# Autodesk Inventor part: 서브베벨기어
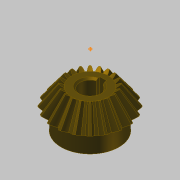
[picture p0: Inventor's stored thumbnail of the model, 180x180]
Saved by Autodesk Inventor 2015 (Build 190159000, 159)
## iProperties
Created: 2018-09
Part Number: 서브베벨기어
Material: 강철, 탄소
Document SubType Name: Modeling
Categories: <?xml version="1.0" encoding="UTF-16"?> <MemberInstance><Categories><FamilyTemplate><FamilyTemplateParameter ValueType="xs:double" Id="1" ObjectReferenceKey="da
Mass: 135.037 g
Surface Area: 63.6444 cm^2
Volume: 17.1585 cm^3
Density: 7.87 g/cm^3
Appearance: 얼룩무늬
CustomPartVersion: 1
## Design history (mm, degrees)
node "맨 위 점"
node "메쉬 평면2"
sketch "톱니 본체 스케치"
  geometry: L1 (0, 0)-(18.003, -31.331); L2 (18.003, -31.331)-(21.664, -28.891); L3 (21.664, -28.891)-(0, 0); L4 (20, -30)-(0, 0); L5 (10.813, -18.818)-(13.012, -17.352); L6 (18.003, -31.331)-(10.813, -18.818); L7 (21.664, -28.891)-(13.012, -17.352); L8 (0, -39.387)-(0, 6.564) reference; L9 (0, -30)-(21.664, -30)
  constraints: 16 end point, 4 point on line, 3 perpendicular, 2 collinear, 1 horizontal alignment, 1 vertical alignment
  dimensions: "d0" = 40 diameter of L4.start L8 (= da_de); "d1" = 36.00616 diameter of L1.end L8 (= da_dfe); "d2" = 43.3282 diameter of L2.end L8 (= da_dae); "d3" = 14.4 distance between parallel lines of L2 L5 (= da_b); "d4" = 28.8906 vertical distance of L2.end L1.start (= da_ve)
revolve "톱니 본체" sketch "톱니 본체 스케치" stored, may be unused: angle "d5" = 90 deg
node "시작점"
node "톱니 평면"
sketch "시작 스케치"
  geometry: L1 (0, -23.505)-(0, 10.645) reference; L2 (-0.834, -2.928)-(0.834, -2.928); A1 r 8.898 centre (-9.698, -3.713) between (-0.834, -2.928) and (-3.903, 3.04); A2 r 8.898 centre (9.698, -3.713) between (3.903, 3.04) and (0.834, -2.928); A3 r 27.357 centre (0, -24.037) between (3.903, 3.04) and (-3.903, 3.04); 1 further point
  constraints: 6 point on circle, 3 centre point, 3 symmetric about line, 2 end point, 1 coincident, 1 perpendicular, 1 other
  dimensions: "d7" = 8.89846 radius of A1 (= fd_rr); "d8" = 9.69794 horizontal distance of point (0, -24.037) A1.centre (= fd_x); "d9" = 20.32439 vertical distance of point (0, -24.037) A1.centre (= fd_y); "d57" = 27.35701 radius of A3 (= 0.5 x fd_dva + 0.3 x da_he); "d58" = 21.10901 distance from line of A3.centre L2 (= 0.5 x fd_dva - 1.12 x da_he)
node "끝점"
  node "끝 평면"
sketch "3D 스케치 오른쪽"
  node "Helical Curve Right" dims "d65" = 229.90621 (computed from da_dm, da_delta, da_beta), "d66" = 31.5, "d67" = 40 (= da_de), "d68" = -5.88003 (= -da_delta), "d69" = 12.16458 (computed from fd_loft, da_delta)
node "끝 평면 오른쪽"
sketch "끝 스케치 오른쪽"
  geometry: L1 (0, -22.649)-(0, 12.15) reference; L2 (-0.497, -1.72)-(0.497, -1.72); A1 r 5.299 centre (-5.775, -2.187) between (-0.497, -1.72) and (-2.324, 1.834); A2 r 5.299 centre (5.775, -2.187) between (2.324, 1.834) and (0.497, -1.72); A3 r 16.291 centre (0, -14.29) between (2.324, 1.834) and (-2.324, 1.834); 1 further point
  constraints: 6 point on circle, 3 centre point, 3 symmetric about line, 2 end point, 1 coincident, 1 perpendicular, 1 other
  dimensions: "d70" = 5.77526 horizontal distance of A3.centre A1.centre (computed from fd_x, fd_ratio); "d71" = 12.10346 vertical distance of point (0, -14.29) A1.centre (computed from fd_y, fd_ratio); "d72" = 5.29916 radius of A1 (computed from fd_rr, fd_ratio); "d73" = 12.57071 distance from line of point (0, -14.29) L2 (computed from d58, fd_ratio); "d74" = 16.29149 radius of A3 (computed from d57, fd_ratio)
feature "로프트 오른쪽" sketch "끝 스케치 오른쪽" dims "d75" = 0, "d77" = 0, "d79" = 0, "d80" = 90 deg, "d85" = 20, "d92" = 90 deg, "d93" = 90 deg, "da_teethtype" = 0 [user parameter]
sketch "3D 스케치 왼쪽"
  node "Helical Curve Left" dims "d26" = 229.90621 (computed from da_dm, da_delta, da_beta), "d27" = 12.16458 (computed from fd_loft, da_delta), "d28" = 40 (= da_de), "d29" = -5.88003 (= -da_delta)
node "끝 평면 왼쪽"
sketch "끝 스케치 왼쪽" dims "d56" = 10.82768 (derived)
  geometry: L1 (0, -35.087)-(0, 18.089) reference; L2 (-0.497, -1.716)-(0.497, -1.716); A1 r 5.299 centre (-5.775, -2.183) between (-0.497, -1.716) and (-2.324, 1.838); A2 r 5.299 centre (5.775, -2.183) between (2.324, 1.838) and (0.497, -1.716); A3 r 16.291 centre (0, -14.287) between (2.324, 1.838) and (-2.324, 1.838); 2 further points; 1 other entity
  constraints: 6 point on circle, 3 centre point, 3 symmetric about line, 2 end point, 1 coincident, 2 other
  dimensions: "d30" = 5.29916 radius of A1 (computed from fd_rr, fd_ratio); "d31" = 5.77526 horizontal distance of point (0, -14.287) A1.centre (computed from fd_x, fd_ratio); "d32" = 12.10346 vertical distance of A1.centre point (0, -14.287) (computed from fd_y, fd_ratio); "d61" = 16.29149 radius of A3 (computed from d57, fd_ratio); "d62" = 12.57071 distance from line of point (0, -14.287) L2 (computed from d58, fd_ratio)
feature "로프트 왼쪽" sketch "끝 스케치 왼쪽" dims "d35" = 0, "d37" = 0, "d39" = 0, "d40" = 90 deg, "d84" = 10, "d90" = 90 deg, "d91" = 90 deg, "da_teethtype" = 0 [user parameter]
sketch "본체 스케치"
  geometry: L1 (0, -35.038)-(0, -19.531) reference; L2 (18.003, -31.331)-(10.813, -18.818) reference; L3 (10.813, -18.818)-(0, -18.818); L4 (18.003, -31.331)-(0, -31.331)
  constraints: 4 end point, 2 perpendicular, 2 point on line
revolve "본체 고정" sketch "본체 스케치" stored, may be unused: angle "d46" = 90 deg
feature "피치 지름" dims angle "d47" = 90 deg
sketch "스케치8"
  geometry: C1 r 17 at (0, 0); 1 further point
  constraints: 1 centre point, 1 coincident
  dimensions: "d94" = 34 diameter of C1
extrude "돌출1" join sketch "스케치8" distance "d95" = 10; taper "d96" = 0 deg
sketch "스케치9"
  geometry: 1 further point
hole "구멍1" sketch "스케치9" at (0, 0) diameter "d97" = 12; stored, may be unused: countersink angle "d101" = 90 deg, drill point angle "d103" = 118 deg; dims "d98" = 6, "d99" = 4, "d100" = 2, "d102" = 8
sketch "스케치10"
  geometry: 1 further point
sketch "스케치11"
  geometry: 1 further point
sketch "스케치12"
  geometry: L1 (-2, 5.657)-(-2, 7.8); L2 (-2, 7.8)-(2, 7.8); L3 (2, 7.8)-(2, 5.657); A1 r 6 centre (0, 0) between (-2, 5.657) and (2, 5.657) reference; 1 further point
  constraints: 6 end point, 2 parallel, 2 point on circle, 1 perpendicular, 1 vertical
  dimensions: "d104" = 4 distance of L1.end L2.end; "d105" = 13.8 dimension on A1 L2
extrude "돌출2" cut sketch "스케치12" stored distance "d106" = 7; taper "d107" = 0 deg
chamfer "모따기1" distance "d108" = 1; stored, may be unused: second distance "d109" = 2, angle "d110" = 45 deg
body "Solid1"
feature "로프트" dims "d17" = 0, "d18" = 90 deg, "d19" = 0, "d20" = 90 deg, "d89" = 0, "da_teethtype" = 0 [user parameter]
pattern_circular "원형 패턴" dims angle "d22" = 360 deg, "d88" = 0, "da_teethtype" = 0 [user parameter]
pattern_circular "원형 패턴 오른쪽" dims angle "d82" = 360 deg, "da_teethtype" = 0 [user parameter]
pattern_circular "원형 패턴 왼쪽" dims angle "d42" = 360 deg, "da_teethtype" = 0 [user parameter]
sketch "끝 스케치"
  geometry: L1 (0, -15.359)-(0, 6.983) reference; L2 (-0.497, -1.72)-(0.497, -1.72); A1 r 5.299 centre (-5.775, -2.187) between (-0.497, -1.72) and (-2.324, 1.834); A2 r 5.299 centre (5.775, -2.187) between (2.324, 1.834) and (0.497, -1.72); A3 r 16.291 centre (0, -14.29) between (2.324, 1.834) and (-2.324, 1.834); 1 further point
  constraints: 6 point on circle, 3 centre point, 3 symmetric about line, 2 end point, 1 coincident, 1 other
  dimensions: "d12" = 5.29916 radius of A1 (computed from fd_rr, fd_ratio); "d15" = 5.77526 horizontal distance of A1.centre point (0, -14.29) (computed from fd_x, fd_ratio); "d16" = 12.10346 vertical distance of A1.centre point (0, -14.29) (computed from fd_y, fd_ratio); "d59" = 16.29149 radius of A3 (computed from d57, fd_ratio); "d60" = 12.57071 distance from line of A3.centre L2 (computed from d58, fd_ratio)
sketch "Sketch6"
  geometry: L1 (20, -30)-(0, 0) reference; L2 (0, -37.8)-(0, 6.3) reference
body "Srf1"
other parameters: "da_b" = 14.4 [user parameter; used in 2 equation terms], "da_de" = 40 [user parameter; used in 4 equation terms], "da_dae" = 43.3282 [user parameter; used in 2 equation terms], "da_dfe" = 36.00616 [user parameter; used in 1 equation term], "da_le" = 36.05551 [user parameter; used in 1 equation term], "da_omega" = 90 deg [user parameter; used in 1 equation term], "da_beta" = 0 [user parameter; used in 2 equation terms], "da_delta" = 5.88003 [user parameter; used in 8 equation terms], "da_alpha" = 20 deg [user parameter; used in 2 equation terms], "da_he" = 4.4 [user parameter; used in 4 equation terms], "da_ve" = 28.8906 [user parameter; used in 1 equation term], "fd_dv" = 48.07402 (computed from da_de, da_delta) [user parameter; used in 1 equation term], "fd_dva" = 52.07402 (computed from da_dae, da_delta) [user parameter; used in 3 equation terms], "fd_dvb" = 45.1748 (computed from fd_dv, da_alpha) [user parameter; used in 2 equation terms], "da_zv" = 240.37008 [user parameter; used in 1 equation term], "fd_loft" = 14.62 (= da_b + 0.05 x da_he) [user parameter; used in 4 equation terms], "fd_ratio" = 5.95514 (computed from da_le, fd_loft) [user parameter; used in 15 equation terms], "fd_rr" = 8.89846 (computed from fd_dd, fd_dvb) [user parameter; used in 6 equation terms], "fd_angle" = 0.66075 (computed from da_zv) [user parameter; used in 4 equation terms], "fd_x1" = 1.58709 (computed from da_dvw, fd_angle) [user parameter; used in 1 equation term], "fd_y1" = 23.98456 (computed from da_dvw, fd_angle) [user parameter; used in 1 equation term], "fd_x2" = 8.11084 (computed from fd_rr, fd_angle2, fd_angle) [user parameter; used in 1 equation term], "fd_y2" = 3.66016 (computed from fd_rr, fd_angle2, fd_angle) [user parameter; used in 1 equation term], "fd_x" = 9.69794 (= fd_x1 + fd_x2) [user parameter; used in 4 equation terms], "fd_y" = 20.32439 (= fd_y1 - fd_y2) [user parameter; used in 4 equation terms], "fd_angle2" = 3.57832 (computed from fd_dvb, fd_dd, da_alpha) [user parameter; used in 2 equation terms], "fd_dd" = 48.55402 (= fd_dva - 0.8 x da_he) [user parameter; used in 2 equation terms], "da_dvw" = 48.07402 [user parameter; used in 2 equation terms], "d11" = 14.62 (= fd_loft), "da_dm" = 32.01232 [user parameter; used in 2 equation terms], "da_x" = 0 [user parameter], "da_m" = 2 [user parameter], "d48" = 0, "d49" = 0, "d50" = 90 deg (= da_omega), "d51" = 9 deg (computed from da_z), "d52" = 0, "d53" = 0, "d54" = 0
